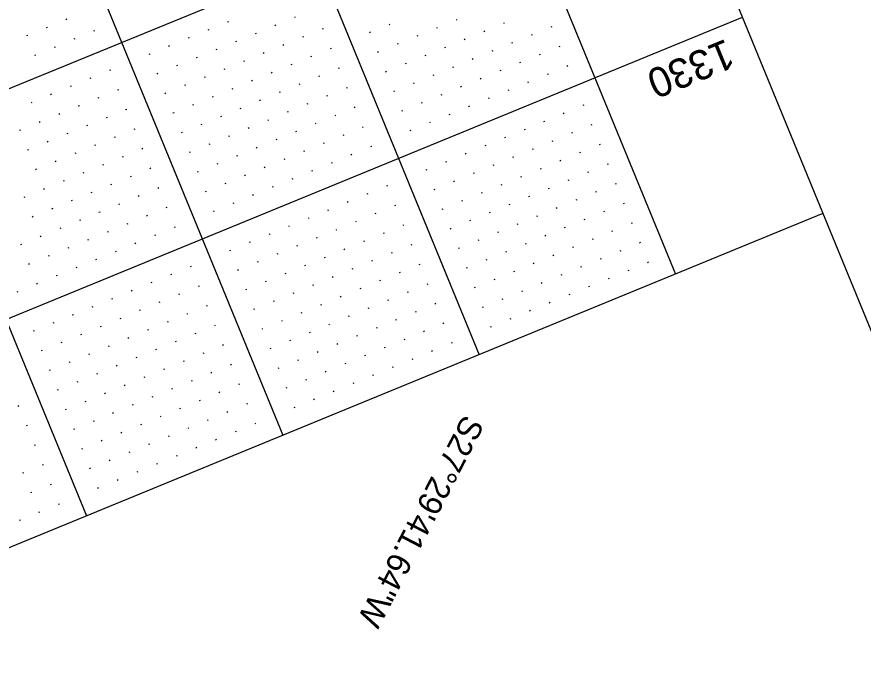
# Model space of a CAD drawing. Extents: x 2148770 to 2150891, y 142633 to 144465.
# Drawn here: x 2150307.4 to 2150506.7, y 143693.5 to 143849.1 of the extents above; entities that cross this region are included whole.
import ezdxf

# ---------------------------------------------------------------- set-up
doc = ezdxf.new("R2010")
doc.units = 0
for name, color, linetype in [('PR_Align_Ramp_B_Label', 7, 'Continuous'), ('SHT_Plan_Profile_Sheet_Elev_Txt', 7, 'Continuous'), ('SHT_Profile_Grid_Major', 7, 'Continuous'), ('SHT_Profile_Grid_Minor', 7, 'Continuous'), ('SHT_Sheet_Border', 7, 'Continuous')]:
    doc.layers.add(name, color=color, linetype=linetype)

msp = doc.modelspace()

# ---------------------------------------------------------------- linework, layer by layer
at = {"layer": 'SHT_Profile_Grid_Major'}
for p, q in [((2150226.36, 144232.01), (2150416.26, 143769.48)), ((2150180.11, 144213.02), (2150370.01, 143750.49)), ((2150133.85, 144194.03), (2150323.76, 143731.5)), ((2150459.23, 143895.22), (2149002.24, 143297.03)), ((2150478.22, 143848.96), (2149021.23, 143250.78))]:
    msp.add_line(p, q, dxfattribs=at)
at = {"layer": 'SHT_Profile_Grid_Minor'}
for p, q in [((2150319.1, 143848.5), (2150318.86, 143848.4)), ((2150357.17, 143847.91), (2150356.94, 143847.82)), ((2150372.94, 143848.98), (2150372.71, 143848.89)), ((2150411.02, 143848.4), (2150410.79, 143848.31)), ((2150314.47, 143846.6), (2150314.24, 143846.5)), ((2150352.54, 143846.01), (2150352.31, 143845.92)), ((2150368.32, 143847.09), (2150368.09, 143846.99)), ((2150379.47, 143846.26), (2150379.24, 143846.16)), ((2150395.24, 143847.33), (2150395.01, 143847.23)), ((2150406.39, 143846.5), (2150406.16, 143846.41)), ((2150422.17, 143847.57), (2150421.94, 143847.48)), ((2150433.32, 143846.75), (2150433.09, 143846.65)), ((2150309.84, 143844.7), (2150309.61, 143844.6)), ((2150320.99, 143843.87), (2150320.76, 143843.78)), ((2150325.62, 143845.77), (2150325.39, 143845.67)), ((2150347.92, 143844.11), (2150347.69, 143844.02)), ((2150363.69, 143845.19), (2150363.46, 143845.09)), ((2150374.84, 143844.36), (2150374.61, 143844.26)), ((2150390.62, 143845.43), (2150390.39, 143845.34)), ((2150401.77, 143844.6), (2150401.54, 143844.51)), ((2150417.54, 143845.67), (2150417.31, 143845.58)), ((2150428.69, 143844.85), (2150428.46, 143844.75)), ((2150316.37, 143841.97), (2150316.14, 143841.88)), ((2150343.29, 143842.22), (2150343.06, 143842.12)), ((2150359.07, 143843.29), (2150358.84, 143843.19)), ((2150370.22, 143842.46), (2150369.99, 143842.36)), ((2150397.14, 143842.7), (2150396.91, 143842.61)), ((2150408.29, 143841.88), (2150408.06, 143841.78)), ((2150412.92, 143843.78), (2150412.69, 143843.68)), ((2150424.07, 143842.95), (2150423.84, 143842.85)), ((2150435.22, 143842.12), (2150434.99, 143842.03)), ((2150311.74, 143840.07), (2150311.51, 143839.98)), ((2150338.67, 143840.32), (2150338.44, 143840.22)), ((2150354.44, 143841.39), (2150354.21, 143841.29)), ((2150365.59, 143840.56), (2150365.36, 143840.47)), ((2150381.37, 143841.63), (2150381.14, 143841.54)), ((2150392.52, 143840.81), (2150392.29, 143840.71)), ((2150403.67, 143839.98), (2150403.44, 143839.88)), ((2150419.44, 143841.05), (2150419.21, 143840.95)), ((2150430.59, 143840.22), (2150430.36, 143840.13)), ((2150349.82, 143839.49), (2150349.59, 143839.39)), ((2150360.97, 143838.66), (2150360.74, 143838.57)), ((2150372.12, 143837.83), (2150371.89, 143837.74)), ((2150376.74, 143839.73), (2150376.51, 143839.64)), ((2150399.04, 143838.08), (2150398.81, 143837.98)), ((2150414.82, 143839.15), (2150414.59, 143839.06)), ((2150425.97, 143838.32), (2150425.74, 143838.23)), ((2150329.42, 143836.52), (2150329.19, 143836.42)), ((2150345.19, 143837.59), (2150344.96, 143837.5)), ((2150356.34, 143836.76), (2150356.11, 143836.67)), ((2150367.49, 143835.94), (2150367.26, 143835.84)), ((2150383.27, 143837.01), (2150383.04, 143836.91)), ((2150394.42, 143836.18), (2150394.19, 143836.08)), ((2150410.19, 143837.25), (2150409.96, 143837.16)), ((2150421.34, 143836.42), (2150421.11, 143836.33)), ((2150437.12, 143837.5), (2150436.89, 143837.4)), ((2150324.79, 143834.62), (2150324.56, 143834.52)), ((2150340.57, 143835.69), (2150340.34, 143835.6)), ((2150351.72, 143834.86), (2150351.49, 143834.77)), ((2150362.87, 143834.04), (2150362.64, 143833.94)), ((2150378.64, 143835.11), (2150378.41, 143835.01)), ((2150405.57, 143835.35), (2150405.34, 143835.26)), ((2150416.72, 143834.53), (2150416.48, 143834.43)), ((2150432.49, 143835.6), (2150432.26, 143835.5)), ((2150320.17, 143832.72), (2150319.94, 143832.63)), ((2150331.32, 143831.89), (2150331.09, 143831.8)), ((2150347.09, 143832.96), (2150346.86, 143832.87)), ((2150358.24, 143832.14), (2150358.01, 143832.04)), ((2150374.02, 143833.21), (2150373.79, 143833.11)), ((2150385.17, 143832.38), (2150384.93, 143832.29)), ((2150400.94, 143833.45), (2150400.71, 143833.36)), ((2150412.09, 143832.63), (2150411.86, 143832.53)), ((2150427.87, 143833.7), (2150427.63, 143833.6)), ((2150315.54, 143830.82), (2150315.31, 143830.73)), ((2150326.69, 143829.99), (2150326.46, 143829.9)), ((2150342.47, 143831.07), (2150342.24, 143830.97)), ((2150353.62, 143830.24), (2150353.38, 143830.14)), ((2150369.39, 143831.31), (2150369.16, 143831.22)), ((2150380.54, 143830.48), (2150380.31, 143830.39)), ((2150396.32, 143831.55), (2150396.08, 143831.46)), ((2150407.47, 143830.73), (2150407.23, 143830.63)), ((2150418.62, 143829.9), (2150418.38, 143829.8)), ((2150423.24, 143831.8), (2150423.01, 143831.7)), ((2150310.92, 143828.92), (2150310.69, 143828.83)), ((2150322.07, 143828.1), (2150321.83, 143828)), ((2150348.99, 143828.34), (2150348.76, 143828.24)), ((2150364.77, 143829.41), (2150364.53, 143829.32)), ((2150375.92, 143828.58), (2150375.68, 143828.49)), ((2150402.84, 143828.83), (2150402.61, 143828.73)), ((2150413.99, 143828), (2150413.76, 143827.91)), ((2150440.91, 143828.25), (2150440.68, 143828.15)), ((2150317.44, 143826.2), (2150317.21, 143826.1)), ((2150333.22, 143827.27), (2150332.98, 143827.17)), ((2150344.37, 143826.44), (2150344.13, 143826.35)), ((2150360.14, 143827.51), (2150359.91, 143827.42)), ((2150371.29, 143826.68), (2150371.06, 143826.59)), ((2150387.07, 143827.76), (2150386.83, 143827.66)), ((2150398.21, 143826.93), (2150397.98, 143826.83)), ((2150409.36, 143826.1), (2150409.13, 143826.01)), ((2150436.29, 143826.35), (2150436.06, 143826.25)), ((2150312.82, 143824.3), (2150312.58, 143824.2)), ((2150328.59, 143825.37), (2150328.36, 143825.27)), ((2150355.52, 143825.61), (2150355.28, 143825.52)), ((2150366.66, 143824.79), (2150366.43, 143824.69)), ((2150377.81, 143823.96), (2150377.58, 143823.86)), ((2150382.44, 143825.86), (2150382.21, 143825.76)), ((2150404.74, 143824.2), (2150404.51, 143824.11)), ((2150431.66, 143824.45), (2150431.43, 143824.35)), ((2150308.19, 143822.4), (2150307.96, 143822.3)), ((2150323.97, 143823.47), (2150323.73, 143823.37)), ((2150335.11, 143822.64), (2150334.88, 143822.55)), ((2150350.89, 143823.71), (2150350.66, 143823.62)), ((2150362.04, 143822.89), (2150361.81, 143822.79)), ((2150373.19, 143822.06), (2150372.96, 143821.96)), ((2150388.96, 143823.13), (2150388.73, 143823.04)), ((2150400.11, 143822.3), (2150399.88, 143822.21)), ((2150427.04, 143822.55), (2150426.81, 143822.45)), ((2150442.81, 143823.62), (2150442.58, 143823.52)), ((2150319.34, 143821.57), (2150319.11, 143821.48)), ((2150330.49, 143820.74), (2150330.26, 143820.65)), ((2150346.26, 143821.82), (2150346.03, 143821.72)), ((2150357.41, 143820.99), (2150357.18, 143820.89)), ((2150368.56, 143820.16), (2150368.33, 143820.07)), ((2150384.34, 143821.23), (2150384.11, 143821.14)), ((2150422.41, 143820.65), (2150422.18, 143820.55)), ((2150438.19, 143821.72), (2150437.96, 143821.63)), ((2150314.71, 143819.67), (2150314.48, 143819.58)), ((2150325.86, 143818.84), (2150325.63, 143818.75)), ((2150337.01, 143818.02), (2150336.78, 143817.92)), ((2150352.79, 143819.09), (2150352.56, 143818.99)), ((2150363.94, 143818.26), (2150363.71, 143818.17)), ((2150379.71, 143819.33), (2150379.48, 143819.24)), ((2150390.86, 143818.51), (2150390.63, 143818.41)), ((2150417.79, 143818.75), (2150417.56, 143818.66)), ((2150428.94, 143817.92), (2150428.71, 143817.83)), ((2150433.56, 143819.82), (2150433.33, 143819.73)), ((2150444.71, 143818.99), (2150444.48, 143818.9)), ((2150310.09, 143817.77), (2150309.86, 143817.68)), ((2150321.24, 143816.95), (2150321.01, 143816.85)), ((2150332.39, 143816.12), (2150332.16, 143816.02)), ((2150348.16, 143817.19), (2150347.93, 143817.09)), ((2150359.31, 143816.36), (2150359.08, 143816.27)), ((2150375.09, 143817.43), (2150374.86, 143817.34)), ((2150386.24, 143816.61), (2150386.01, 143816.51)), ((2150413.16, 143816.85), (2150412.93, 143816.76)), ((2150424.31, 143816.02), (2150424.08, 143815.93)), ((2150440.09, 143817.1), (2150439.86, 143817)), ((2150316.61, 143815.05), (2150316.38, 143814.95)), ((2150327.76, 143814.22), (2150327.53, 143814.12)), ((2150354.69, 143814.46), (2150354.46, 143814.37)), ((2150370.46, 143815.54), (2150370.23, 143815.44)), ((2150381.61, 143814.71), (2150381.38, 143814.61)), ((2150408.54, 143814.95), (2150408.31, 143814.86)), ((2150419.69, 143814.12), (2150419.46, 143814.03)), ((2150435.46, 143815.2), (2150435.23, 143815.1)), ((2150446.61, 143814.37), (2150446.38, 143814.27)), ((2150311.99, 143813.15), (2150311.76, 143813.05)), ((2150323.14, 143812.32), (2150322.91, 143812.23)), ((2150338.91, 143813.39), (2150338.68, 143813.3)), ((2150350.06, 143812.56), (2150349.83, 143812.47)), ((2150365.84, 143813.64), (2150365.61, 143813.54)), ((2150376.99, 143812.81), (2150376.76, 143812.71)), ((2150403.91, 143813.05), (2150403.68, 143812.96)), ((2150415.06, 143812.23), (2150414.83, 143812.13)), ((2150430.84, 143813.3), (2150430.61, 143813.2)), ((2150441.99, 143812.47), (2150441.76, 143812.38)), ((2150318.51, 143810.42), (2150318.28, 143810.33)), ((2150334.29, 143811.49), (2150334.06, 143811.4)), ((2150361.21, 143811.74), (2150360.98, 143811.64)), ((2150372.36, 143810.91), (2150372.13, 143810.81)), ((2150410.44, 143810.33), (2150410.21, 143810.23)), ((2150426.21, 143811.4), (2150425.98, 143811.3)), ((2150437.36, 143810.57), (2150437.13, 143810.48)), ((2150313.89, 143808.52), (2150313.66, 143808.43)), ((2150329.66, 143809.59), (2150329.43, 143809.5)), ((2150340.81, 143808.77), (2150340.58, 143808.67)), ((2150356.59, 143809.84), (2150356.36, 143809.74)), ((2150367.74, 143809.01), (2150367.51, 143808.92)), ((2150394.66, 143809.26), (2150394.43, 143809.16)), ((2150405.81, 143808.43), (2150405.58, 143808.33)), ((2150421.59, 143809.5), (2150421.35, 143809.4)), ((2150432.74, 143808.67), (2150432.5, 143808.58)), ((2150448.51, 143809.74), (2150448.28, 143809.65)), ((2150309.26, 143806.62), (2150309.03, 143806.53)), ((2150325.04, 143807.69), (2150324.81, 143807.6)), ((2150336.19, 143806.87), (2150335.96, 143806.77)), ((2150351.96, 143807.94), (2150351.73, 143807.84)), ((2150363.11, 143807.11), (2150362.88, 143807.02)), ((2150390.04, 143807.36), (2150389.8, 143807.26)), ((2150416.96, 143807.6), (2150416.73, 143807.51)), ((2150428.11, 143806.77), (2150427.88, 143806.68)), ((2150443.89, 143807.84), (2150443.65, 143807.75)), ((2150320.41, 143805.8), (2150320.18, 143805.7)), ((2150331.56, 143804.97), (2150331.33, 143804.87)), ((2150342.71, 143804.14), (2150342.48, 143804.05)), ((2150358.49, 143805.21), (2150358.25, 143805.12)), ((2150385.41, 143805.46), (2150385.18, 143805.36)), ((2150396.56, 143804.63), (2150396.33, 143804.53)), ((2150412.34, 143805.7), (2150412.1, 143805.61)), ((2150423.48, 143804.87), (2150423.25, 143804.78)), ((2150434.63, 143804.05), (2150434.4, 143803.95)), ((2150439.26, 143805.95), (2150439.03, 143805.85)), ((2150450.41, 143805.12), (2150450.18, 143805.02)), ((2150311.16, 143802), (2150310.93, 143801.9)), ((2150315.79, 143803.9), (2150315.55, 143803.8)), ((2150326.94, 143803.07), (2150326.7, 143802.97)), ((2150338.09, 143802.24), (2150337.85, 143802.15)), ((2150353.86, 143803.31), (2150353.63, 143803.22)), ((2150380.79, 143803.56), (2150380.55, 143803.46)), ((2150391.93, 143802.73), (2150391.7, 143802.64)), ((2150407.71, 143803.8), (2150407.48, 143803.71)), ((2150418.86, 143802.98), (2150418.63, 143802.88)), ((2150430.01, 143802.15), (2150429.78, 143802.05)), ((2150445.78, 143803.22), (2150445.55, 143803.12)), ((2150322.31, 143801.17), (2150322.08, 143801.08)), ((2150333.46, 143800.34), (2150333.23, 143800.25)), ((2150376.16, 143801.66), (2150375.93, 143801.56)), ((2150387.31, 143800.83), (2150387.08, 143800.74)), ((2150398.46, 143800), (2150398.23, 143799.91)), ((2150414.23, 143801.08), (2150414, 143800.98)), ((2150425.38, 143800.25), (2150425.15, 143800.15)), ((2150441.16, 143801.32), (2150440.93, 143801.23)), ((2150452.31, 143800.49), (2150452.08, 143800.4)), ((2150317.69, 143799.27), (2150317.45, 143799.18)), ((2150328.83, 143798.44), (2150328.6, 143798.35)), ((2150344.61, 143799.52), (2150344.38, 143799.42)), ((2150371.53, 143799.76), (2150371.3, 143799.67)), ((2150382.68, 143798.93), (2150382.45, 143798.84)), ((2150393.83, 143798.11), (2150393.6, 143798.01)), ((2150409.61, 143799.18), (2150409.38, 143799.08)), ((2150420.76, 143798.35), (2150420.53, 143798.25)), ((2150436.53, 143799.42), (2150436.3, 143799.33)), ((2150447.68, 143798.59), (2150447.45, 143798.5)), ((2150313.06, 143797.37), (2150312.83, 143797.28)), ((2150324.21, 143796.55), (2150323.98, 143796.45)), ((2150339.98, 143797.62), (2150339.75, 143797.52)), ((2150366.91, 143797.86), (2150366.68, 143797.77)), ((2150378.06, 143797.03), (2150377.83, 143796.94)), ((2150389.21, 143796.21), (2150388.98, 143796.11)), ((2150416.13, 143796.45), (2150415.9, 143796.36)), ((2150431.91, 143797.52), (2150431.68, 143797.43)), ((2150443.06, 143796.7), (2150442.83, 143796.6)), ((2150308.43, 143795.47), (2150308.2, 143795.38)), ((2150319.58, 143794.65), (2150319.35, 143794.55)), ((2150335.36, 143795.72), (2150335.13, 143795.62)), ((2150357.66, 143794.06), (2150357.43, 143793.97)), ((2150362.28, 143795.96), (2150362.05, 143795.87)), ((2150373.43, 143795.13), (2150373.2, 143795.04)), ((2150384.58, 143794.31), (2150384.35, 143794.21)), ((2150400.36, 143795.38), (2150400.13, 143795.28)), ((2150411.51, 143794.55), (2150411.28, 143794.46)), ((2150427.28, 143795.62), (2150427.05, 143795.53)), ((2150438.43, 143794.8), (2150438.2, 143794.7)), ((2150454.21, 143795.87), (2150453.98, 143795.77)), ((2150314.96, 143792.75), (2150314.73, 143792.65)), ((2150330.73, 143793.82), (2150330.5, 143793.72)), ((2150368.81, 143793.24), (2150368.58, 143793.14)), ((2150379.96, 143792.41), (2150379.73, 143792.31)), ((2150395.73, 143793.48), (2150395.5, 143793.39)), ((2150422.66, 143793.72), (2150422.43, 143793.63)), ((2150433.81, 143792.9), (2150433.58, 143792.8)), ((2150444.96, 143792.07), (2150444.73, 143791.97)), ((2150449.58, 143793.97), (2150449.35, 143793.87)), ((2150310.33, 143790.85), (2150310.1, 143790.75)), ((2150321.48, 143790.02), (2150321.25, 143789.93)), ((2150326.11, 143791.92), (2150325.88, 143791.82)), ((2150348.41, 143790.26), (2150348.18, 143790.17)), ((2150364.18, 143791.34), (2150363.95, 143791.24)), ((2150375.33, 143790.51), (2150375.1, 143790.41)), ((2150391.11, 143791.58), (2150390.88, 143791.49)), ((2150402.26, 143790.75), (2150402.03, 143790.66)), ((2150418.03, 143791.83), (2150417.8, 143791.73)), ((2150429.18, 143791), (2150428.95, 143790.9)), ((2150440.33, 143790.17), (2150440.1, 143790.08)), ((2150456.11, 143791.24), (2150455.88, 143791.15)), ((2150316.86, 143788.12), (2150316.63, 143788.03)), ((2150343.78, 143788.37), (2150343.55, 143788.27)), ((2150359.56, 143789.44), (2150359.33, 143789.34)), ((2150370.71, 143788.61), (2150370.48, 143788.52)), ((2150386.48, 143789.68), (2150386.25, 143789.59)), ((2150397.63, 143788.85), (2150397.4, 143788.76)), ((2150413.41, 143789.93), (2150413.18, 143789.83)), ((2150424.56, 143789.1), (2150424.33, 143789)), ((2150435.71, 143788.27), (2150435.48, 143788.18)), ((2150451.48, 143789.34), (2150451.25, 143789.25)), ((2150312.23, 143786.22), (2150312, 143786.13)), ((2150339.16, 143786.47), (2150338.93, 143786.37)), ((2150366.08, 143786.71), (2150365.85, 143786.62)), ((2150381.86, 143787.78), (2150381.63, 143787.69)), ((2150393.01, 143786.96), (2150392.78, 143786.86)), ((2150404.16, 143786.13), (2150403.92, 143786.03)), ((2150419.93, 143787.2), (2150419.7, 143787.11)), ((2150431.08, 143786.37), (2150430.85, 143786.28)), ((2150446.86, 143787.44), (2150446.62, 143787.35)), ((2150307.61, 143784.32), (2150307.38, 143784.23)), ((2150334.53, 143784.57), (2150334.3, 143784.47)), ((2150350.31, 143785.64), (2150350.08, 143785.54)), ((2150361.46, 143784.81), (2150361.23, 143784.72)), ((2150377.23, 143785.88), (2150377, 143785.79)), ((2150388.38, 143785.06), (2150388.15, 143784.96)), ((2150399.53, 143784.23), (2150399.3, 143784.13)), ((2150415.31, 143785.3), (2150415.07, 143785.21)), ((2150426.46, 143784.47), (2150426.22, 143784.38)), ((2150442.23, 143785.55), (2150442, 143785.45)), ((2150329.91, 143782.67), (2150329.68, 143782.57)), ((2150345.68, 143783.74), (2150345.45, 143783.65)), ((2150367.98, 143782.09), (2150367.75, 143781.99)), ((2150372.61, 143783.99), (2150372.37, 143783.89)), ((2150383.76, 143783.16), (2150383.52, 143783.06)), ((2150394.91, 143782.33), (2150394.67, 143782.24)), ((2150421.83, 143782.57), (2150421.6, 143782.48)), ((2150437.61, 143783.65), (2150437.37, 143783.55)), ((2150325.28, 143780.77), (2150325.05, 143780.68)), ((2150341.06, 143781.84), (2150340.82, 143781.75)), ((2150352.21, 143781.01), (2150351.97, 143780.92)), ((2150363.36, 143780.19), (2150363.12, 143780.09)), ((2150379.13, 143781.26), (2150378.9, 143781.16)), ((2150390.28, 143780.43), (2150390.05, 143780.34)), ((2150406.06, 143781.5), (2150405.82, 143781.41)), ((2150417.2, 143780.68), (2150416.97, 143780.58)), ((2150432.98, 143781.75), (2150432.75, 143781.65)), ((2150320.66, 143778.87), (2150320.42, 143778.78)), ((2150336.43, 143779.94), (2150336.2, 143779.85)), ((2150347.58, 143779.12), (2150347.35, 143779.02)), ((2150374.51, 143779.36), (2150374.27, 143779.26)), ((2150385.65, 143778.53), (2150385.42, 143778.44)), ((2150401.43, 143779.6), (2150401.2, 143779.51)), ((2150428.35, 143779.85), (2150428.12, 143779.75)), ((2150316.03, 143776.97), (2150315.8, 143776.88)), ((2150327.18, 143776.14), (2150326.95, 143776.05)), ((2150331.81, 143778.04), (2150331.57, 143777.95)), ((2150342.96, 143777.22), (2150342.72, 143777.12)), ((2150354.1, 143776.39), (2150353.87, 143776.29)), ((2150369.88, 143777.46), (2150369.65, 143777.37)), ((2150381.03, 143776.63), (2150380.8, 143776.54)), ((2150396.8, 143777.71), (2150396.57, 143777.61)), ((2150407.95, 143776.88), (2150407.72, 143776.78)), ((2150423.73, 143777.95), (2150423.5, 143777.85)), ((2150311.41, 143775.07), (2150311.17, 143774.98)), ((2150322.55, 143774.25), (2150322.32, 143774.15)), ((2150338.33, 143775.32), (2150338.1, 143775.22)), ((2150349.48, 143774.49), (2150349.25, 143774.4)), ((2150365.25, 143775.56), (2150365.02, 143775.47)), ((2150376.4, 143774.73), (2150376.17, 143774.64)), ((2150392.18, 143775.81), (2150391.95, 143775.71)), ((2150403.33, 143774.98), (2150403.1, 143774.88)), ((2150419.1, 143776.05), (2150418.87, 143775.96)), ((2150317.93, 143772.35), (2150317.7, 143772.25)), ((2150333.7, 143773.42), (2150333.47, 143773.32)), ((2150344.85, 143772.59), (2150344.62, 143772.5)), ((2150371.78, 143772.84), (2150371.55, 143772.74)), ((2150387.55, 143773.91), (2150387.32, 143773.81)), ((2150398.7, 143773.08), (2150398.47, 143772.98)), ((2150409.85, 143772.25), (2150409.62, 143772.16)), ((2150313.3, 143770.45), (2150313.07, 143770.35)), ((2150329.08, 143771.52), (2150328.85, 143771.42)), ((2150340.23, 143770.69), (2150340, 143770.6)), ((2150356, 143771.76), (2150355.77, 143771.67)), ((2150367.15, 143770.94), (2150366.92, 143770.84)), ((2150378.3, 143770.11), (2150378.07, 143770.01)), ((2150382.93, 143772.01), (2150382.7, 143771.91)), ((2150394.08, 143771.18), (2150393.85, 143771.09)), ((2150405.23, 143770.35), (2150405, 143770.26)), ((2150324.45, 143769.62), (2150324.22, 143769.53)), ((2150335.6, 143768.79), (2150335.37, 143768.7)), ((2150351.38, 143769.86), (2150351.15, 143769.77)), ((2150373.68, 143768.21), (2150373.45, 143768.12)), ((2150389.45, 143769.28), (2150389.22, 143769.19)), ((2150400.6, 143768.45), (2150400.37, 143768.36)), ((2150319.83, 143767.72), (2150319.6, 143767.63)), ((2150330.98, 143766.89), (2150330.75, 143766.8)), ((2150346.75, 143767.97), (2150346.52, 143767.87)), ((2150357.9, 143767.14), (2150357.67, 143767.04)), ((2150369.05, 143766.31), (2150368.82, 143766.22)), ((2150384.83, 143767.38), (2150384.6, 143767.29)), ((2150395.98, 143766.56), (2150395.75, 143766.46)), ((2150315.2, 143765.82), (2150314.97, 143765.73)), ((2150326.35, 143765), (2150326.12, 143764.9)), ((2150337.5, 143764.17), (2150337.27, 143764.07)), ((2150342.13, 143766.07), (2150341.9, 143765.97)), ((2150353.28, 143765.24), (2150353.05, 143765.14)), ((2150380.2, 143765.48), (2150379.97, 143765.39)), ((2150391.35, 143764.66), (2150391.12, 143764.56)), ((2150321.73, 143763.1), (2150321.5, 143763)), ((2150332.88, 143762.27), (2150332.65, 143762.17)), ((2150348.65, 143763.34), (2150348.42, 143763.25)), ((2150359.8, 143762.51), (2150359.57, 143762.42)), ((2150375.58, 143763.58), (2150375.35, 143763.49)), ((2150386.73, 143762.76), (2150386.5, 143762.66)), ((2150317.1, 143761.2), (2150316.87, 143761.1)), ((2150328.25, 143760.37), (2150328.02, 143760.27)), ((2150344.03, 143761.44), (2150343.8, 143761.35)), ((2150355.18, 143760.61), (2150354.95, 143760.52)), ((2150370.95, 143761.69), (2150370.72, 143761.59)), ((2150382.1, 143760.86), (2150381.87, 143760.76)), ((2150323.63, 143758.47), (2150323.4, 143758.38)), ((2150339.4, 143759.54), (2150339.17, 143759.45)), ((2150350.55, 143758.71), (2150350.32, 143758.62)), ((2150377.48, 143758.96), (2150377.24, 143758.86)), ((2150307.85, 143757.4), (2150307.62, 143757.3)), ((2150319, 143756.57), (2150318.77, 143756.48)), ((2150334.78, 143757.64), (2150334.54, 143757.55)), ((2150345.93, 143756.82), (2150345.69, 143756.72)), ((2150361.7, 143757.89), (2150361.47, 143757.79)), ((2150372.85, 143757.06), (2150372.62, 143756.97)), ((2150330.15, 143755.74), (2150329.92, 143755.65)), ((2150341.3, 143754.92), (2150341.07, 143754.82)), ((2150357.08, 143755.99), (2150356.84, 143755.89)), ((2150309.75, 143752.77), (2150309.52, 143752.68)), ((2150325.53, 143753.85), (2150325.29, 143753.75)), ((2150336.68, 143753.02), (2150336.44, 143752.92)), ((2150347.82, 143752.19), (2150347.59, 143752.1)), ((2150352.45, 143754.09), (2150352.22, 143753.99)), ((2150363.6, 143753.26), (2150363.37, 143753.17)), ((2150320.9, 143751.95), (2150320.67, 143751.85)), ((2150332.05, 143751.12), (2150331.82, 143751.02)), ((2150343.2, 143750.29), (2150342.97, 143750.2)), ((2150358.97, 143751.36), (2150358.74, 143751.27)), ((2150327.42, 143749.22), (2150327.19, 143749.13)), ((2150338.57, 143748.39), (2150338.34, 143748.3)), ((2150354.35, 143749.46), (2150354.12, 143749.37)), ((2150311.65, 143748.15), (2150311.42, 143748.05)), ((2150322.8, 143747.32), (2150322.57, 143747.23)), ((2150333.95, 143746.49), (2150333.72, 143746.4)), ((2150349.72, 143747.57), (2150349.49, 143747.47)), ((2150329.32, 143744.59), (2150329.09, 143744.5)), ((2150345.1, 143745.67), (2150344.87, 143745.57)), ((2150313.55, 143743.52), (2150313.32, 143743.43)), ((2150324.7, 143742.7), (2150324.47, 143742.6)), ((2150340.47, 143743.77), (2150340.24, 143743.67)), ((2150308.92, 143741.62), (2150308.69, 143741.53)), ((2150335.85, 143741.87), (2150335.62, 143741.77)), ((2150315.45, 143738.9), (2150315.22, 143738.8)), ((2150331.22, 143739.97), (2150330.99, 143739.87)), ((2150310.82, 143737), (2150310.59, 143736.9)), ((2150326.6, 143738.07), (2150326.37, 143737.98)), ((2150317.35, 143734.27), (2150317.12, 143734.18)), ((2150312.72, 143732.37), (2150312.49, 143732.28)), ((2150308.1, 143730.47), (2150307.86, 143730.38))]:
    msp.add_line(p, q, dxfattribs=at)
at = {"layer": 'SHT_Sheet_Border'}
for p, q in [((2150272.62, 144251), (2150462.52, 143788.47)), ((2150497.21, 143802.71), (2149040.22, 143204.53))]:
    msp.add_line(p, q, dxfattribs=at)
msp.add_lwpolyline([(2150699.45, 143310.11), (2149242.47, 142711.93), (2148843.68, 143683.25), (2150300.66, 144281.43)], close=True, dxfattribs=at)

# ---------------------------------------------------------------- texts
at = {"layer": 'PR_Align_Ramp_B_Label'}
msp.add_text('S27%%d29\'41.64"W', height=5.6, rotation=242.5051, dxfattribs=at).set_placement((2150412.65, 143755.63))
at = {"layer": 'SHT_Plan_Profile_Sheet_Elev_Txt'}
msp.add_text('1330', height=7, rotation=202.3213, dxfattribs=at).set_placement((2150474.43, 143844))

doc.saveas('drawing.dxf')
